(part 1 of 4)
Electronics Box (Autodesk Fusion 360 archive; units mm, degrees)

design "Electronics Box" references "USB host shield", "Teensy 4.1", "BTS790 Motor Driver", "half proto board"
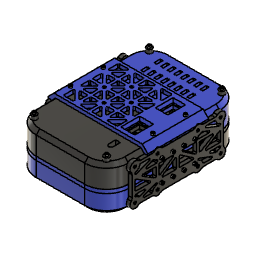
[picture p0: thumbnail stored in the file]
parameter "threadedinsertdiam" = 4.4
parameter "m3screwdiam" = 3.4
parameter "d454" = 6.4625 (= "0.1875 in + ( m3screwdiam / 2 )")
component_insert "Component Insert1"
component_insert "Component Insert2"
component_insert "Component Insert3"
position "Position2"
position "Position3"
component_insert "Component Insert4"
rectangular_pattern "Ё" uSpaceDistance 53 vSpaceDistance 0
rectangular_pattern "Ё" uSpaceDistance -53 vSpaceDistance 0
copy_paste "CutPaste1"
copy_paste "CutPaste2"
copy_paste "CutPaste3"
copy_paste "CutPaste4"
copy_paste "CutPaste5"
copy_paste "CutPaste6"
copy_paste "CutPaste7"
copy_paste "CutPaste8"
copy_paste "CutPaste1"
copy_paste "CutPaste2"
copy_paste "CutPaste3"
position "Position4"
position "Position5"
position "Position6"
position "Position7"
position "Position8"
sketch "Sketch1" plane through (0, 0, -1.65) normal (0, 0, -1) x axis (1, 0, 0)
  line L1 (-25, -25) -> (78, -25)
  line L2 (-25, 184) -> (-25, -25)
  line L3 (78, 184) -> (-25, 184)
  line L4 (78, -25) -> (78, 184)
  line L5 (-31.35, 190.35) -> (-31.35, -31.35)
  line L6 (84.35, 190.35) -> (-31.35, 190.35)
  line L7 (84.35, -31.35) -> (84.35, 190.35)
  line L8 (-31.35, -31.35) -> (84.35, -31.35)
  line L9 (-37.7, 196.7) -> (-37.7, -37.7)
  line L10 (90.7, 196.7) -> (-37.7, 196.7)
  line L11 (90.7, -37.7) -> (90.7, 196.7)
  line L12 (-37.7, -37.7) -> (90.7, -37.7)
  line L13 (90.7, -31.35) -> (84.35, -31.35)
  line L14 (90.7, 190.35) -> (84.35, 190.35)
  circle C1 centre (-20, 179) radius 1.5
  circle C2 centre (20, 179) radius 1.5
  circle C3 centre (20, 139) radius 1.5
  circle C4 centre (-20, 139) radius 1.5
  circle C5 centre (33, 179) radius 1.5
  circle C6 centre (73, 179) radius 1.5
  circle C7 centre (33, 139) radius 1.5
  circle C8 centre (73, 139) radius 1.5
  circle C9 centre (73, 126) radius 1.5
  circle C10 centre (33, 126) radius 1.5
  circle C11 centre (20, 126) radius 1.5
  circle C12 centre (-20, 126) radius 1.5
  circle C13 centre (-20, 86) radius 1.5
  circle C14 centre (20, 86) radius 1.5
  circle C15 centre (20, 73) radius 1.5
  circle C16 centre (20, 33) radius 1.5
  circle C17 centre (-20, 33) radius 1.5
  circle C18 centre (-20, 73) radius 1.5
  circle C19 centre (33, 73) radius 1.5
  circle C20 centre (73, 73) radius 1.5
  circle C21 centre (73, 33) radius 1.5
  circle C22 centre (33, 33) radius 1.5
  circle C23 centre (33, 20) radius 1.5
  circle C24 centre (73, 20) radius 1.5
  circle C25 centre (73, -20) radius 1.5
  circle C26 centre (33, -20) radius 1.5
  circle C27 centre (-20, -20) radius 1.5
  circle C28 centre (20, -20) radius 1.5
  circle C29 centre (20, 20) radius 1.5
  circle C30 centre (-20, 20) radius 1.5
  point P8 (73.5, -25)
  point P9 (78, -20.5)
  point P2 (-25, 179.5)
  point P3 (-20.5, 184)
  point P48 (90.7, -31.35)
  point P49 (90.7, 190.35)
  horizontal L1
  vertical L2
  horizontal L3
  vertical L4
  coincident L1 P8
  coincident L4 P9
  coincident P2 L2
  coincident P3 L3
  coincident L11 P48
  perpendicular L11 L13
  coincident L11 P49
  perpendicular L11 L14
  dimension "d11" = -6.35
  dimension "d12" = -12.7
extrude "Extrude1" new body sketch "Sketch1" profile of C1 C2 C3 C4 C5 C6 C7 C8 C9 C10 C11 C12 C13 C14 C15 C16 C17 C18 C19 C20 C21 C22 C23 C24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 along normal blind 6.35
extrude "Extrude2" add sketch "Sketch1" profile of L5 L6 L8 L11 L9 L10 L12 L13 L14 against normal blind 32
position "Position9"
sketch "Sketch2" plane through (0, 0, 30.35) normal (0, 0, 1) x axis (-1, 0, 0)
  line L1 (-90.7, -31.35) -> (31.35, -31.35)
  line L2 (-90.7, -37.7) -> (-90.7, -31.35)
  line L3 (37.7, -37.7) -> (-90.7, -37.7)
  line L4 (37.7, 196.7) -> (37.7, -37.7)
  line L5 (-90.7, 196.7) -> (37.7, 196.7)
  line L6 (-90.7, 190.35) -> (-90.7, 196.7)
  line L7 (31.35, 190.35) -> (-90.7, 190.35)
  line L8 (31.35, -31.35) -> (31.35, 190.35)
position "Position10"
sketch "Sketch3" plane through (0, 0, 30.35) normal (0, 0, 1) x axis (-1, 0, 0)
  line L1 (-90.7, -31.35) -> (31.35, -31.35)
  line L2 (-90.7, -37.7) -> (-90.7, -31.35)
  line L3 (37.7, -37.7) -> (-90.7, -37.7)
  line L4 (37.7, 196.7) -> (37.7, -37.7)
  line L5 (-90.7, 196.7) -> (37.7, 196.7)
  line L6 (-90.7, 190.35) -> (-90.7, 196.7)
  line L7 (31.35, 190.35) -> (-90.7, 190.35)
  line L8 (31.35, -31.35) -> (31.35, 190.35)
  line L9 (22.075, 30.875) -> (-54.725, 30.875)
  line L10 (-60.825, 141.175) -> (-60.825, 181.075)
  line L11 (14.175, 30.875) -> (31.35, 30.875)
  line L12 (14.175, 190.35) -> (14.175, 30.875)
  line L13 (31.35, 190.35) -> (14.175, 190.35)
  line L14 (31.35, 30.875) -> (31.35, 190.35)
  line L15 (-60.825, 30.875) -> (-46.825, 30.875)
  line L16 (-60.825, 190.35) -> (-60.825, 30.875)
  line L17 (-46.825, 190.35) -> (-60.825, 190.35)
  line L18 (-46.825, 30.875) -> (-46.825, 190.35)
  line L19 (-60.825, 30.875) -> (31.35, 30.875)
  line L20 (-60.825, 16.875) -> (-60.825, 30.875)
  line L21 (31.35, 16.875) -> (-60.825, 16.875)
  line L22 (31.35, 30.875) -> (31.35, 16.875)
  circle C1 centre (-53.175, 56.925) radius 1.5
  circle C2 centre (20.525, 56.925) radius 1.5
  point P9 (31.35, 190.35)
  point P17 (31.35, 190.35)
  point P11 (22.075, 30.875)
  point P8 (-90.7, 190.35)
  point P10 (-54.725, 30.875)
  point P13 (-60.825, 141.175)
  point P19 (-60.825, 30.875)
  point P23 (20.525, 56.925)
  point P22 (-53.175, 56.925)
  point P24 (-60.825, 30.875)
  point P25 (-60.825, 16.875)
  horizontal L11
  vertical L12
  horizontal L13
  vertical L14
  coincident P9 P17
  coincident P11 L11
  horizontal L15
  vertical L16
  horizontal L17
  vertical L18
  coincident P8 L17
  coincident P10 L15
  coincident P13 L16
  horizontal L19
  vertical L20
  horizontal L21
  vertical L22
  coincident P19 L20
  dimension "d15" distance L12 P23 = 6.35
  dimension "d16" distance L18 P22 = 6.35
  dimension "d19" distance P24 P25 = 14
extrude "Extrude3" add sketch "Sketch3" profile of L7 L8 L9 L10 L11 L12 L13 L14 L15 L16 L17 L18 C1 C2 L19 L20 L21 L22 against normal blind 6.35
component_insert "Component Insert5"
position "Position11"
component_insert "Component Insert6"
position "Position12"
position "Position13"
position "Position14"
position "Position15"
position "Position16"
position "Position17"
position "Position18"
position "Position19"
extrude "Extrude4" new body sketch "Sketch3" profile of L1 L2 L3 L4 L5 L6 L7 L8 L13 L14 L17 L22 along normal blind 25.4
sketch "Sketch4" plane through (0, 0, 55.75) normal (0, 0, 1) x axis (-1, 0, 0)
  line L1 (37.7, -37.7) -> (-90.7, -37.7)
  line L2 (37.7, 196.7) -> (37.7, -37.7)
  line L3 (-90.7, 196.7) -> (37.7, 196.7)
  line L4 (-90.7, -37.7) -> (-90.7, 196.7)
  point P3 (37.7, 196.7)
  point P6 (37.7, 196.7)
  point P2 (-90.7, -37.7)
  point P4 (-90.7, -37.7)
  horizontal L1
  vertical L2
  horizontal L3
  vertical L4
  coincident P3 P6
  coincident P2 P4
extrude "Extrude5" add sketch "Sketch4" along normal blind 6.35
sketch "Sketch5" plane through (-37.7, 0, 0) normal (-1, 0, 0) x axis (0, -1, 0)
  line L1 (115.3556, 46) -> (99.3556, 46)
  line L2 (115.3556, 53) -> (115.3556, 46)
  line L3 (99.3556, 53) -> (115.3556, 53)
  line L4 (99.3556, 46) -> (99.3556, 53)
  line L5 (121.7056, 39.65) -> (93.0056, 39.65)
  line L6 (121.7056, 59.35) -> (121.7056, 39.65)
  line L7 (93.0056, 59.35) -> (121.7056, 59.35)
  line L8 (93.0056, 39.65) -> (93.0056, 59.35)
  line L9 (93.0056, 59.35) -> (121.7056, 59.35)
  line L10 (93.0056, 68.4778) -> (93.0056, 59.35)
  line L11 (121.7056, 68.4778) -> (93.0056, 68.4778)
  line L12 (121.7056, 59.35) -> (121.7056, 68.4778)
  line L13 (163.2111, 46) -> (155.7111, 46)
  line L14 (163.2111, 49.07) -> (163.2111, 46)
  line L15 (155.7111, 49.07) -> (163.2111, 49.07)
  line L16 (155.7111, 46) -> (155.7111, 49.07)
  line L17 (169.5611, 39.65) -> (149.3611, 39.65)
  line L18 (169.5611, 55.42) -> (169.5611, 39.65)
  line L19 (149.3611, 55.42) -> (169.5611, 55.42)
  line L20 (149.3611, 39.65) -> (149.3611, 55.42)
  horizontal L9
  vertical L10
  horizontal L11
  vertical L12
  dimension "d24" = 6.35
  dimension "d25" = 6.35
copy_paste "CutPaste1"
copy_paste "CutPaste2"
copy_paste "CutPaste3"
copy_paste "CutPaste4"
extrude "Extrude6" cut sketch "Sketch5" profile of L13 L14 L15 L16 L17 L18 L19 L20 against normal blind 10.16
extrude "Extrude7" cut sketch "Sketch5" profile of L1 L2 L3 L4 L5 L6 L7 L8 L9 L10 L11 L12 against normal blind 25.4
sketch "Sketch6" plane through (0, 0, 62.1) normal (0, 0, 1) x axis (-1, 0, 0)
  line L1 (37.7, 121.7056) -> (12.3, 121.7056)
  line L2 (37.7, 196.7) -> (37.7, 121.7056)
  line L3 (-90.7, 196.7) -> (37.7, 196.7)
  line L4 (-90.7, -37.7) -> (-90.7, 196.7)
  line L5 (37.7, -37.7) -> (-90.7, -37.7)
  line L6 (37.7, 93.0056) -> (37.7, -37.7)
  line L7 (12.3, 93.0056) -> (37.7, 93.0056)
  line L8 (12.3, 121.7056) -> (12.3, 93.0056)
  line L9 (-60.825, 16.875) -> (31.35, 16.875)
  line L10 (-90.7, -31.35) -> (31.35, -31.35)
  line L11 (31.35, -31.35) -> (31.35, 190.35)
  line L12 (23.4125, -1.3625) -> (19.3525, -1.3625)
  line L13 (23.4125, 8.9375) -> (23.4125, -1.3625)
  line L14 (19.3525, 8.9375) -> (23.4125, 8.9375)
  line L15 (19.3525, -1.3625) -> (19.3525, 8.9375)
  line L16 (23.4125, 8.9375) -> (19.3525, -1.3625)
  line L17 (19.3525, 8.9375) -> (23.4125, -1.3625)
  line L18 (14.59, 13.7) -> (28.175, 13.7)
  line L19 (14.59, -6.125) -> (14.59, 13.7)
  line L20 (28.175, -6.125) -> (14.59, -6.125)
  line L21 (28.175, 13.7) -> (28.175, -6.125)
  line L22 (23.4125, -17.0625) -> (19.3525, -17.0625)
  line L23 (23.4125, -6.7625) -> (23.4125, -17.0625)
  line L24 (19.3525, -6.7625) -> (23.4125, -6.7625)
  line L25 (19.3525, -17.0625) -> (19.3525, -6.7625)
  line L26 (23.4125, -6.7625) -> (19.3525, -17.0625)
  line L27 (19.3525, -6.7625) -> (23.4125, -17.0625)
  line L28 (28.175, -2) -> (28.175, -21.825)
  line L29 (14.59, -2) -> (28.175, -2)
  line L30 (14.59, -21.825) -> (14.59, -2)
  line L31 (28.175, -21.825) -> (14.59, -21.825)
  point P20 (21.3825, 3.7875)
  point P29 (21.3825, -11.9125)
  point P16 (19.3525, -1.3625)
  point P17 (23.4125, -1.3625)
  point P19 (19.3525, 8.9375)
  point P25 (19.3525, -17.0625)
  point P26 (23.4125, -17.0625)
  point P28 (19.3525, -6.7625)
  horizontal L12
  perpendicular L12 L13
  parallel L12 L14
  parallel L13 L15
  coincident L16 P20
  coincident L17 P20
  horizontal L22
  perpendicular L22 L23
  parallel L22 L24
  parallel L23 L25
  coincident L26 P29
  coincident L27 P29
  dimension "d36" distance P16 P17 = 4.06
  dimension "d37" distance P16 P19 = 10.3
  dimension "d38" = 4.7625 (= "( 3 / 16 ) * 1 in")
  dimension "d39" distance L11 L21 = 3.175 (= "( 1 / 8 ) * 1 in")
  dimension "d40" distance L9 L18 = 3.175 (= "( 1 / 8 ) * 1 in")
  dimension "d47" distance P25 P26 = 4.06 (= "d36")
  dimension "d48" distance P25 P28 = 10.3 (= "d37")
  dimension "d49" = 4.7625 (= "( 3 / 16 ) * 1 in")
  dimension "d50" distance L11 L28 = 3.175 (= "d39")
  dimension "d51" distance L10 L31 = 9.525
sketch "Sketch7" plane through (0, 0, 62.1) normal (0, 0, 1) x axis (-1, 0, 0)
  line L1 (-74.31, 13.7) -> (28.175, 13.7)
  line L2 (-74.31, -21.825) -> (-74.31, 13.7)
  line L3 (28.175, -21.825) -> (-74.31, -21.825)
  line L4 (28.175, 13.7) -> (28.175, -21.825)
  point P2 (28.175, 13.7)
  point P3 (28.175, 13.7)
  horizontal L1
  vertical L2
  horizontal L3
  vertical L4
  coincident P2 P3
extrude "Extrude13" cut of existing geometry blind -0.3302
extrude "Extrude14" add of existing geometry blind 0.0002 (= "7.791E-06 in")
split "Split1"
split "Split2"
split "Split3"
combine "Combine2"
extrude "Extrude15" new body of existing geometry blind 25.4
extrude "Extrude16" new body of existing geometry blind 25.4
combine "Combine3"
combine "Combine4"
extrude "Extrude17" new body of existing geometry blind 6.35
extrude "Extrude18" add of existing geometry blind 223.52
extrude "Extrude19" new body of existing geometry blind 32.004
combine "Combine5"
combine "Combine6"
extrude "Extrude21" add of existing geometry blind 2.54
extrude "Extrude22" cut of existing geometry blind -27.94
position "Position20"
extrude "Extrude23" add of existing geometry blind 12.7
extrude "Extrude24" add of existing geometry blind 12.7
extrude "Extrude25" cut of existing geometry blind -12.7
split "Split4"
extrude "Extrude26" cut of existing geometry blind -12.7
move_face "MoveFace1"
fillet "Fillet2" radius 31.75
fillet "Fillet3" radius 38.1
chamfer "Chamfer3" distance 6.35
chamfer "Chamfer2" distance 2.6303
sketch "Sketch10" plane through (0, 0, 62.1) normal (0, 0, 1) x axis (-1, 0, 0)
  line L1 (-84.35, -31.35) -> (-0.4, -31.35)
  line L2 (-84.35, 14.65) -> (-84.35, -31.35)
  line L3 (-0.4, 14.65) -> (-84.35, 14.65)
  line L4 (-0.4, -31.35) -> (-0.4, 14.65)
  line L5 (-4.46, 14.65) -> (-0.4, 14.65)
  line L6 (-4.46, 4.35) -> (-4.46, 14.65)
  line L7 (-0.4, 4.35) -> (-4.46, 4.35)
  line L8 (-0.4, 14.65) -> (-0.4, 4.35)
  line L9 (-4.46, -8.35) -> (-0.4, -8.35)
  line L10 (-4.46, -18.65) -> (-4.46, -8.35)
  line L11 (-0.4, -18.65) -> (-4.46, -18.65)
  line L12 (-0.4, -8.35) -> (-0.4, -18.65)
  point P2 (-0.4, -31.35)
  point P4 (-0.4, -31.35)
  point P3 (-84.35, -31.35)
  point P5 (-84.35, -31.35)
  point P11 (-0.4, -8.35)
  point P9 (-4.46, 4.35)
  point P10 (-0.4, 4.35)
  point P8 (-4.46, 14.65)
  point P13 (-4.46, -18.65)
  point P14 (-0.4, -18.65)
  point P12 (-4.46, -8.35)
  horizontal L1
  vertical L2
  horizontal L3
  vertical L4
  coincident P2 P4
  coincident P3 P5
  horizontal L5
  vertical L6
  horizontal L7
  vertical L8
  horizontal L9
  vertical L10
  horizontal L11
  vertical L12
  coincident L4 P11
  dimension "d112" distance P9 P10 = 4.06
  dimension "d113" distance P8 P9 = 10.3
  dimension "d114" distance P13 P14 = 4.06 (= "d112")
  dimension "d115" distance P12 P13 = 10.3 (= "d113")
  dimension "d116" distance L1 L11 = 12.7
  dimension "d117" distance L7 L9 = 12.7
extrude "Extrude28" cut sketch "Sketch10" profile of L5 L6 L7 L8 L9 L10 L11 L12 against normal blind 27.94
rectangular_pattern "R-Pattern2" uSpaceDistance -79.89 (= "-3.3051181102362204 in + 4.06 mm") vSpaceDistance 0
sketch "Sketch11" plane through (0, 0, 55.75) normal (0, 0, -1) x axis (1, 0, 0)
  line L1 (84.35, 14.65) -> (80.29, 14.65)
  line L2 (84.35, 4.35) -> (84.35, 14.65)
  line L3 (80.29, 4.35) -> (84.35, 4.35)
  line L4 (80.29, 14.65) -> (80.29, 4.35)
  line L5 (84.35, -8.35) -> (80.29, -8.35)
  line L6 (84.35, -18.65) -> (84.35, -8.35)
  line L7 (80.29, -18.65) -> (84.35, -18.65)
  line L8 (80.29, -8.35) -> (80.29, -18.65)
  line L9 (72.9371, 14.65) -> (68.8771, 14.65)
  line L10 (72.9371, 4.35) -> (72.9371, 14.65)
  line L11 (68.8771, 4.35) -> (72.9371, 4.35)
  line L12 (68.8771, 14.65) -> (68.8771, 4.35)
  line L13 (72.9371, -8.35) -> (68.8771, -8.35)
  line L14 (72.9371, -18.65) -> (72.9371, -8.35)
  line L15 (68.8771, -18.65) -> (72.9371, -18.65)
  line L16 (68.8771, -8.35) -> (68.8771, -18.65)
  line L17 (61.5243, 14.65) -> (57.4643, 14.65)
  line L18 (61.5243, 4.35) -> (61.5243, 14.65)
  line L19 (57.4643, 4.35) -> (61.5243, 4.35)
  line L20 (57.4643, 14.65) -> (57.4643, 4.35)
  line L21 (61.5243, -8.35) -> (57.4643, -8.35)
  line L22 (61.5243, -18.65) -> (61.5243, -8.35)
  line L23 (57.4643, -18.65) -> (61.5243, -18.65)
  line L24 (57.4643, -8.35) -> (57.4643, -18.65)
  line L25 (50.1114, 14.65) -> (46.0514, 14.65)
  line L26 (50.1114, 4.35) -> (50.1114, 14.65)
  line L27 (46.0514, 4.35) -> (50.1114, 4.35)
  line L28 (46.0514, 14.65) -> (46.0514, 4.35)
  line L29 (50.1114, -8.35) -> (46.0514, -8.35)
  line L30 (50.1114, -18.65) -> (50.1114, -8.35)
  line L31 (46.0514, -18.65) -> (50.1114, -18.65)
  line L32 (46.0514, -8.35) -> (46.0514, -18.65)
  line L33 (38.6986, 14.65) -> (34.6386, 14.65)
  line L34 (38.6986, 4.35) -> (38.6986, 14.65)
  line L35 (34.6386, 4.35) -> (38.6986, 4.35)
  line L36 (34.6386, 14.65) -> (34.6386, 4.35)
  line L37 (38.6986, -8.35) -> (34.6386, -8.35)
  line L38 (38.6986, -18.65) -> (38.6986, -8.35)
  line L39 (34.6386, -18.65) -> (38.6986, -18.65)
  line L40 (34.6386, -8.35) -> (34.6386, -18.65)
  line L41 (27.2857, 14.65) -> (23.2257, 14.65)
  line L42 (27.2857, 4.35) -> (27.2857, 14.65)
  line L43 (23.2257, 4.35) -> (27.2857, 4.35)
  line L44 (23.2257, 14.65) -> (23.2257, 4.35)
  line L45 (27.2857, -8.35) -> (23.2257, -8.35)
  line L46 (27.2857, -18.65) -> (27.2857, -8.35)
  line L47 (23.2257, -18.65) -> (27.2857, -18.65)
  line L48 (23.2257, -8.35) -> (23.2257, -18.65)
  line L49 (15.8729, 14.65) -> (11.8129, 14.65)
  line L50 (15.8729, 4.35) -> (15.8729, 14.65)
  line L51 (11.8129, 4.35) -> (15.8729, 4.35)
  line L52 (11.8129, 14.65) -> (11.8129, 4.35)
  line L53 (15.8729, -8.35) -> (11.8129, -8.35)
  line L54 (15.8729, -18.65) -> (15.8729, -8.35)
  line L55 (11.8129, -18.65) -> (15.8729, -18.65)
  line L56 (11.8129, -8.35) -> (11.8129, -18.65)
  line L57 (4.46, 14.65) -> (0.4, 14.65)
  line L58 (4.46, 4.35) -> (4.46, 14.65)
  line L59 (0.4, 4.35) -> (4.46, 4.35)
  line L60 (0.4, 14.65) -> (0.4, 4.35)
  line L61 (4.46, -8.35) -> (0.4, -8.35)
  line L62 (4.46, -18.65) -> (4.46, -8.35)
  line L63 (0.4, -18.65) -> (4.46, -18.65)
  line L64 (0.4, -8.35) -> (0.4, -18.65)
  line L65 (90.7, 21) -> (-5.95, 21)
  line L66 (90.7, -34.525) -> (90.7, 21)
  line L67 (-5.95, -34.525) -> (90.7, -34.525)
  line L68 (-5.95, 21) -> (-5.95, -34.525)
  point P64 (4.46, -18.65)
  point P62 (0.4, -8.35)
  point P59 (4.46, 14.65)
  point P7 (84.35, -8.35)
  horizontal L65
  vertical L66
  horizontal L67
  vertical L68
  dimension "d124" distance P64 L67 = 15.875
  dimension "d125" distance P62 L68 = 6.35
  dimension "d126" distance P59 L65 = 6.35 (= "d125")
  dimension "d127" distance P7 L66 = 6.35 (= "d125")
extrude "Extrude29" add sketch "Sketch11" profile of L1 L2 L3 L4 L5 L6 L7 L8 L9 L10 L11 L12 L13 L14 L15 L16 L17 L18 L19 L20 L21 L22 L23 L24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 along normal blind 18
work_plane "WorkPlane2"
extrude "Extrude30" cut of existing geometry blind -0.8056
extrude "Extrude31" cut of existing geometry blind -0.8056
split "Split5"
extrude "Extrude34" new body of existing geometry blind 61.6204
extrude "Extrude35" new body of existing geometry blind 41.8846
combine "Combine7"
fillet "Fillet4" radius 38.1
split "Split6"
split "Split7"
remove_body "RemoveBody1"
remove_body "RemoveBody2"
position "Position21"
extrude "Extrude36" cut of existing geometry blind -12.7
extrude "Extrude37" add of existing geometry blind 12.7
split "Split8"
extrude "Extrude38" add of existing geometry blind 35.56
delete_face "DeleteFace1"
sketch "Sketch14" plane through (0, 0, 30.35) normal (0, 0, 1) x axis (-1, 0, 0)
  line L1 (-84.3454, -37.7096) -> (-0.4, -37.7096)
  line L2 (1.475, 79.5) -> (37.7, 79.5)
  line L3 (1.475, 18.175) -> (1.475, 79.5)
  line L4 (-59.525, 18.175) -> (1.475, 18.175)
  line L5 (-59.525, 79.5) -> (-59.525, 18.175)
  line L6 (-122.4454, 79.5) -> (-59.525, 79.5)
  line L7 (-122.4454, 0.3904) -> (-122.4454, 79.5)
  line L8 (-0.4, -37.7096) -> (-84.3454, -37.7096)
  line L9 (37.7, 79.5) -> (37.7, 0.3904)
  line L10 (37.7, 79.5) -> (1.475, 79.5)
  line L11 (37.7, 158.6) -> (37.7, 79.5)
  line L12 (-84.3454, 196.7) -> (-0.4, 196.7)
  line L13 (-122.4454, 79.5) -> (-122.4454, 158.6)
  line L14 (-59.525, 79.5) -> (-122.4454, 79.5)
  line L15 (-59.525, 177.65) -> (-59.525, 79.5)
  line L16 (1.475, 177.65) -> (-59.525, 177.65)
  line L17 (1.475, 79.5) -> (1.475, 177.65)
  line L18 (14.175, 92.2) -> (14.175, 179.4021)
  line L19 (25, 92.2) -> (14.175, 92.2)
  line L20 (25, 158.6) -> (25, 92.2)
  line L21 (-72.225, 184) -> (-72.225, 92.2)
  line L22 (-84.3454, 184) -> (-72.225, 184)
  line L23 (-109.7454, 92.2) -> (-109.7454, 158.6)
  line L24 (-72.225, 92.2) -> (-109.7454, 92.2)
  line L25 (-0.4, -25.0096) -> (-84.3454, -25.0096)
  line L26 (25, 66.8) -> (25, 0.3904)
  line L27 (14.175, 66.8) -> (25, 66.8)
  line L28 (14.175, 5.475) -> (14.175, 66.8)
  line L29 (-72.225, 5.475) -> (14.175, 5.475)
  line L30 (-72.225, 66.8) -> (-72.225, 5.475)
  line L31 (-109.7454, 66.8) -> (-72.225, 66.8)
  line L32 (-109.7454, 0.3904) -> (-109.7454, 66.8)
  line L33 (-109.7454, 92.2) -> (-109.7454, 66.8)
  line L34 (-72.225, 18.175) -> (14.175, 18.175)
  line L35 (-109.7454, 5.475) -> (-72.225, 5.475)
  line L36 (-73.525, 184) -> (-73.525, 5.475)
  line L37 (25, 18.175) -> (14.175, 18.175)
  line L38 (-73.525, 18.175) -> (-72.225, 18.175)
  arc A1 centre (-84.3454, 0.3904) radius 38.1 clockwise from (-84.3454, -37.7096) to (-122.4454, 0.3904)
  arc A2 centre (-0.4, 0.3904) radius 38.1 clockwise from (37.7, 0.3904) to (-0.4, -37.7096)
  arc A3 centre (-0.4, 158.6) radius 38.1 clockwise from (-0.4, 196.7) to (37.7, 158.6)
  arc A4 centre (-84.3454, 158.6) radius 38.1 clockwise from (-122.4454, 158.6) to (-84.3454, 196.7)
  arc A5 centre (-0.4, 158.6) radius 25.4 clockwise from (14.175, 179.4021) to (25, 158.6)
  arc A6 centre (-84.3454, 158.6) radius 25.4 clockwise from (-109.7454, 158.6) to (-84.3454, 184)
  arc A7 centre (-0.4, 0.3904) radius 25.4 clockwise from (25, 0.3904) to (-0.4, -25.0096)
  arc A8 centre (-84.3454, 0.3904) radius 25.4 clockwise from (-84.3454, -25.0096) to (-109.7454, 0.3904)
  point P51 (14.175, 18.175)
  point P52 (-72.225, 18.175)
  point P6 (1.475, 18.175)
  point P55 (-109.7454, 5.475)
  point P56 (-73.525, 5.475)
  point P53 (-73.525, 24.275)
  point P58 (25, 18.175)
  point P59 (-73.525, 18.175)
  coincident L28 P51
  coincident L30 P52
  perpendicular L30 L34
  coincident P6 L34
  coincident L32 P55
  perpendicular L32 L35
  coincident L35 P56
  perpendicular L35 L36
  coincident P53 L36
  coincident L26 P58
  perpendicular L26 L37
  coincident L36 P59
  perpendicular L36 L38
  dimension "d158" = -12.7
  dimension "d159" = -12.7
extrude "Extrude39" cut sketch "Sketch14" profile of L4 L6 L14 A6 L24 L22 L23 L31 L25 L28 A7 L26 L29 L30 L32 A8 L33 L34 L35 L36 L37 L38 against normal blind 20.32
extrude "Extrude40" add of existing geometry blind 3.175
extrude "Extrude41" add of existing geometry blind 43.18
sketch "Sketch15" plane through (0, -79.5, 0) normal (0, -1, 0) x axis (1, 0, 0)
  line L1 (122.45, 30.35) -> (116.1, 30.35)
  line L2 (122.45, 55.75) -> (122.45, 30.35)
  line L3 (116.1, 62.1) -> (122.45, 55.75)
  line L4 (-31.35, 62.1) -> (116.1, 62.1)
  line L5 (-37.7, 55.75) -> (-31.35, 62.1)
  line L6 (-37.7, 30.35) -> (-37.7, 55.75)
  line L7 (-31.35, 30.35) -> (-37.7, 30.35)
  line L8 (-31.35, 53.1197) -> (-31.35, 30.35)
  line L9 (-28.7197, 55.75) -> (-31.35, 53.1197)
  line L10 (113.4697, 55.75) -> (-28.7197, 55.75)
  line L11 (116.1, 53.1197) -> (113.4697, 55.75)
  line L12 (116.1, 30.35) -> (116.1, 53.1197)
  line L13 (116.1, 62.1) -> (-31.35, 62.1)
  line L14 (116.1, 62.1) -> (122.45, 55.75)
  line L15 (122.45, -8) -> (122.45, 55.75)
  point P17 (-31.35, 62.1)
  point P18 (-31.35, 62.1)
  point P16 (116.1, 62.1)
  point P19 (116.1, 62.1)
  point P15 (122.45, 55.75)
  point P20 (122.45, 55.75)
  point P14 (122.45, -8)
  point P21 (122.45, -8)
  coincident P17 P18
  coincident P16 P19
  coincident P15 P20
  coincident P14 P21
sketch "Sketch16" plane through (0, 0, -8) normal (0, 0, -1) x axis (1, 0, 0)
  line L1 (-37.7, 79.5) -> (122.45, 79.5)
  line L2 (-37.7, 0.4) -> (-37.7, 79.5)
  line L3 (84.35, -37.7) -> (0.4, -37.7)
  line L4 (122.45, 79.5) -> (122.45, 0.4)
  line L5 (128.8, 79.5) -> (122.45, 79.5)
  line L6 (128.8, 41.4) -> (128.8, 79.5)
  line L7 (122.45, 41.4) -> (128.8, 41.4)
  line L8 (122.45, 79.5) -> (122.45, 41.4)
  arc A1 centre (0.4, 0.4) radius 38.1 clockwise from (0.4, -37.7) to (-37.7, 0.4)
  arc A2 centre (84.35, 0.4) radius 38.1 clockwise from (122.45, 0.4) to (84.35, -37.7)
  point P2 (122.45, 79.5)
  point P11 (122.45, 79.5)
  point P13 (128.8, 41.4)
  point P14 (122.45, 41.4)
  point P12 (128.8, 79.5)
  horizontal L5
  vertical L6
  horizontal L7
  vertical L8
  coincident P2 P11
  dimension "d166" distance P13 P14 = 6.35
  dimension "d167" distance P12 P13 = 38.1
sweep "Sweep2" sketch "Sketch16" TwistAngle 0 TaperAngle 0
extrude "Extrude42" cut of existing geometry blind -139.7
sketch "Sketch17" plane through (128.8, 0, 0) normal (1, 0, 0) x axis (0, 1, 0)
  line L1 (-41.4, -8) -> (-79.5, -8)
  line L2 (-41.4, 58.3803) -> (-41.4, -8)
  line L3 (-79.5, 58.3803) -> (-41.4, 58.3803)
  line L4 (-79.5, -8) -> (-79.5, 58.3803)
  line L5 (-79.5, 24) -> (-79.5, -1.65)
  line L6 (-0.4, 24) -> (-79.5, 24)
  line L7 (-0.4, -1.65) -> (-0.4, 24)
  line L8 (-79.5, -1.65) -> (-0.4, -1.65)
  line L9 (-41.4, 58.3803) -> (-41.4, -8)
  line L10 (-79.5, 30.35) -> (-0.4, 30.35)
  line L11 (-79.5, 53.1197) -> (-79.5, 30.35)
  line L12 (-0.4, 53.1197) -> (-79.5, 53.1197)
  line L13 (-0.4, 30.35) -> (-0.4, 53.1197)
  line L14 (-41.4, 41.7349) -> (-79.5, 41.7349)
  line L15 (-41.4, 11.175) -> (-79.5, 11.175)
  point P16 (-79.5, 41.7349)
  point P17 (-41.4, 41.7349)
  point P18 (-79.5, 11.175)
  point P19 (-41.4, 11.175)
  point P20 (-69.975, 11.175)
  point P21 (-50.925, 11.175)
  point P22 (-50.925, 41.7349)
  point P23 (-69.975, 41.7349)
  midpoint L11 P16
  coincident L9 P17
  perpendicular L9 L14
  midpoint L5 P18
  coincident L9 P19
  perpendicular L9 L15
  coincident L15 P20
  coincident L15 P21
  coincident L14 P22
  coincident L14 P23
  dimension "d180" distance P18 P20 = 9.525
  dimension "d181" distance P19 P21 = 9.525 (= "d180")
  dimension "d182" distance P16 P23 = 9.525 (= "d180")
  dimension "d183" distance P17 P22 = 9.525 (= "d180")
hole "Hole1" HoleDepth 25.4 HoleDiameter 3.4 (= "m3screwdiam") TipAngle 180
sketch "Sketch18" plane through (122.45, 0, 0) normal (1, 0, 0) x axis (0, 1, 0)
  line L1 (-79.5, -8) -> (-79.5, 24)
  line L2 (-0.4, -8) -> (-79.5, -8)
  line L3 (-0.4, 24) -> (-0.4, -8)
  line L4 (-79.5, 24) -> (-0.4, 24)
hole "Hole2" HoleDepth 177.8 HoleDiameter 4.4 (= "threadedinsertdiam") TipAngle 180
mirror "Mirror3" mirrorStitchTolerance 0.1016
mirror "Mirror1" mirrorStitchTolerance 0.1016
work_plane "WorkPlane5"
mirror "Mirror2" mirrorStitchTolerance 0.1016
sketch "Sketch19" plane through (122.45, 0, 0) normal (1, 0, 0) x axis (0, 1, 0)
  line L1 (-79.5, 30.35) -> (-158.6, 30.35)
  line L2 (-158.6, 55.75) -> (-79.5, 55.75)
  line L3 (-158.6, 30.35) -> (-158.6, 55.75)
  line L4 (-41.4, -8) -> (-117.6, -8)
  line L5 (-41.4, 58.3803) -> (-41.4, -8)
  line L6 (-117.6, 58.3803) -> (-41.4, 58.3803)
  line L7 (-117.6, -8) -> (-117.6, 58.3803)
  circle C1 centre (-108.075, 11.175) radius 1.7
  circle C2 centre (-89.025, 41.7349) radius 1.7
  circle C3 centre (-108.075, 41.7349) radius 1.7
  circle C4 centre (-89.025, 11.175) radius 1.7
  circle C5 centre (-69.975, 11.175) radius 1.7
  circle C6 centre (-50.925, 41.7349) radius 1.7
  circle C7 centre (-69.975, 41.7349) radius 1.7
  circle C8 centre (-50.925, 11.175) radius 1.7
hole "Hole3" HoleDepth 190.5 HoleDiameter 4.4 (= "threadedinsertdiam") TipAngle 180
sketch "Sketch20" plane through (0, 0, -1.65) normal (0, 0, 1) x axis (-1, 0, 0)
  line L1 (-116.1, 0.4) -> (-116.1, 79.5)
  line L2 (31.35, 79.5) -> (31.35, 0.4)
  line L3 (-106.8006, -22.0506) -> (-84.35, 0.4)
  line L4 (-124.8544, -28.0129) -> (-111.2908, -14.4492)
  line L5 (-99.1992, -26.5408) -> (-112.7629, -40.1044)
  line L6 (-118.8086, -34.0586) -> (-105.245, -20.495)
  line L7 (-83.1465, 51.2) -> (-116.1, 51.2)
  line L8 (-136.6984, 59.75) -> (-113.9, 59.75)
  line L9 (-113.9, 42.65) -> (-136.6984, 42.65)
  line L10 (-136.6984, 51.2) -> (-113.9, 51.2)
  line L11 (-122.45, 0.4) -> (-122.45, 79.5)
  arc A1 centre (-84.35, 0.4) radius 31.75 clockwise from (-84.35, -31.35) to (-116.1, 0.4)
  arc A2 centre (-0.4, 0.4) radius 31.75 clockwise from (31.35, 0.4) to (-0.4, -31.35)
  circle C1 centre (-105.245, -20.495) radius 2.2
  circle C2 centre (-105.245, -20.495) radius 8.55
  arc A3 centre (-118.8086, -34.0586) radius 8.55 clockwise from (-112.7629, -40.1044) to (-124.8544, -28.0129)
  arc A4 centre (-105.245, -20.495) radius 8.55 clockwise from (-111.2908, -14.4492) to (-99.1992, -26.5408)
  arc A5 centre (-84.35, 0.4) radius 38.1 clockwise from (-84.35, -37.7) to (-122.45, 0.4)
  circle C3 centre (-113.9, 51.2) radius 2.2
  circle C4 centre (-113.9, 51.2) radius 8.55
  arc A6 centre (-136.6984, 51.2) radius 8.55 clockwise from (-136.6984, 42.65) to (-136.6984, 59.75)
  arc A7 centre (-113.9, 51.2) radius 8.55 clockwise from (-113.9, 59.75) to (-113.9, 42.65)
  point P4 (-84.35, 0.4)
  point P12 (-84.35, 0.4)
  point P13 (-106.8006, -22.0506)
  point P10 (-105.245, -20.495)
  point P18 (-105.245, -20.495)
  point P23 (-116.1, 51.2)
  point P25 (-116.1, 51.2)
  point P24 (-113.9, 51.2)
  point P32 (-113.9, 51.2)
  point P2 (-116.1, 0.4)
  coincident P4 P12
  midpoint A1 P13
  coincident P10 L3
  tangent L4 A3
  tangent A3 L5
  parallel L4 L5
  tangent L5 A4
  tangent L4 A4
  coincident P10 P18
  collinear L3 L6
  tangent C2 A4
  coincident L1 P23
  coincident P23 P25
  perpendicular L1 L7
  coincident P24 L7
  tangent L8 A6
  tangent A6 L9
  parallel L8 L9
  tangent L9 A7
  tangent L8 A7
  perpendicular L1 L10
  coincident P24 P32
  tangent C4 A7
  tangent A1 C1
  tangent L1 C3
  dimension "d197" diameter C1 = 4.4 (= "threadedinsertdiam")
  dimension "d198" = 6.35
  dimension "d199" distance P2 P23 = 50.8
  dimension "d200" diameter C3 = 4.4 (= "threadedinsertdiam")
  dimension "d201" = 6.35
extrude "Extrude43" new body sketch "Sketch20" profile of A1 L1 C1 L4 L5 A4 C3 L8 L9 A7 along normal blind 25.65
sketch "Sketch21" plane through (0, 0, 24) normal (0, 0, 1) x axis (-1, 0, 0)
  line L1 (-116.1, 59.75) -> (-113.9, 59.75)
  line L2 (-116.1, 42.65) -> (-116.1, 59.75)
  line L3 (-113.9, 42.65) -> (-116.1, 42.65)
  arc A1 centre (-113.9, 51.2) radius 8.55 clockwise from (-113.9, 59.75) to (-113.9, 42.65)
hole "Hole4" HoleDepth 10 HoleDiameter 4.4 (= "threadedinsertdiam") TipAngle 180
mirror "Mirror4" mirrorStitchTolerance 0.1016
mirror "Mirror5" mirrorStitchTolerance 0.1016
extrude "Extrude46" new body of existing geometry blind 15.24
extrude "Extrude47" new body of existing geometry blind 12.7
combine "Combine8"
combine "Combine9"
sketch "Sketch22" plane through (0, 0, 30.35) normal (0, 0, 1) x axis (-1, 0, 0)
  line L1 (-73.525, 79.5) -> (-73.525, 184)
  line L2 (-59.525, 79.5) -> (-73.525, 79.5)
  line L3 (-59.525, 174.475) -> (-59.525, 79.5)
  line L4 (1.475, 174.475) -> (-59.525, 174.475)
  line L5 (1.475, 79.5) -> (1.475, 174.475)
  line L6 (37.7, 79.5) -> (1.475, 79.5)
  line L7 (37.7, 158.6) -> (37.7, 79.5)
  line L8 (-84.3454, 196.7) -> (-0.4, 196.7)
  line L9 (-122.4454, 79.5) -> (-122.4454, 158.6)
  line L10 (-109.7454, 79.5) -> (-122.4454, 79.5)
  line L11 (-109.7454, 158.6) -> (-109.7454, 79.5)
  line L12 (-73.525, 184) -> (-84.3454, 184)
  line L13 (-59.525, 18.175) -> (-109.7454, 18.175)
  line L14 (-59.525, 79.5) -> (-59.525, 18.175)
  line L15 (-122.4454, 79.5) -> (-59.525, 79.5)
  line L16 (-122.4454, 0.3904) -> (-122.4454, 79.5)
  line L17 (-0.4, -37.7096) -> (-84.3454, -37.7096)
  line L18 (37.7, 79.5) -> (37.7, 0.3904)
  line L19 (1.475, 79.5) -> (37.7, 79.5)
  line L20 (1.475, 18.175) -> (1.475, 79.5)
  line L21 (25, 18.175) -> (1.475, 18.175)
  line L22 (25, 0.3904) -> (25, 18.175)
  line L23 (-84.3454, -25.0096) -> (-0.4, -25.0096)
  line L24 (-109.7454, 18.175) -> (-109.7454, 0.3904)
  line L25 (-0.4, 190.35) -> (-84.35, 190.35)
  line L26 (14.4492, 185.5408) -> (15.1755, 186.267)
  line L27 (27.267, 174.1755) -> (26.5408, 173.4492)
  line L28 (31.35, 116.35) -> (31.35, 158.6)
  line L29 (29.15, 116.35) -> (31.35, 116.35)
  line L30 (31.35, 99.25) -> (29.15, 99.25)
  line L31 (31.35, 79.5) -> (31.35, 99.25)
  line L32 (37.7, 79.5) -> (31.35, 79.5)
  line L33 (37.7, 158.6) -> (37.7, 79.5)
  line L34 (-84.35, 196.7) -> (-0.4, 196.7)
  line L35 (-122.45, 79.5) -> (-122.45, 158.6)
  line L36 (-116.1, 79.5) -> (-122.45, 79.5)
  line L37 (-116.1, 99.25) -> (-116.1, 79.5)
  line L38 (-113.9, 99.25) -> (-116.1, 99.25)
  line L39 (-116.1, 116.35) -> (-113.9, 116.35)
  line L40 (-116.1, 158.6) -> (-116.1, 116.35)
  line L41 (-111.2908, 173.4492) -> (-112.017, 174.1755)
  line L42 (-99.9255, 186.267) -> (-99.1992, 185.5408)
  line L43 (-116.1, 79.5) -> (-116.1, 59.75)
  line L44 (-122.45, 79.5) -> (-116.1, 79.5)
  line L45 (-122.45, 0.4) -> (-122.45, 79.5)
  line L46 (-0.4, -37.7) -> (-84.35, -37.7)
  line L47 (37.7, 79.5) -> (37.7, 0.4)
  line L48 (31.35, 79.5) -> (37.7, 79.5)
  line L49 (31.35, 59.75) -> (31.35, 79.5)
  line L50 (29.15, 59.75) -> (31.35, 59.75)
  line L51 (31.35, 42.65) -> (29.15, 42.65)
  line L52 (31.35, 0.4) -> (31.35, 42.65)
  line L53 (26.5408, -14.4492) -> (27.267, -15.1755)
  line L54 (15.1755, -27.267) -> (14.4492, -26.5408)
  line L55 (-84.35, -31.35) -> (-0.4, -31.35)
  line L56 (-99.1992, -26.5408) -> (-99.9255, -27.267)
  line L57 (-112.017, -15.1755) -> (-111.2908, -14.4492)
  line L58 (-116.1, 42.65) -> (-116.1, 0.4)
  line L59 (-113.9, 42.65) -> (-116.1, 42.65)
  line L60 (-116.1, 59.75) -> (-113.9, 59.75)
  arc A1 centre (-0.4, 158.6) radius 38.1 clockwise from (-0.4, 196.7) to (37.7, 158.6)
  arc A2 centre (-84.3454, 158.6) radius 38.1 clockwise from (-122.4454, 158.6) to (-84.3454, 196.7)
  arc A3 centre (-84.3454, 158.6) radius 25.4 clockwise from (-109.7454, 158.6) to (-84.3454, 184)
  arc A4 centre (-113.9, 107.8) radius 8.55 clockwise from (-113.9, 116.35) to (-113.9, 99.25)
  arc A5 centre (-105.245, 179.495) radius 8.55 clockwise from (-99.1992, 185.5408) to (-111.2908, 173.4492)
  arc A6 centre (-105.245, -20.495) radius 8.55 clockwise from (-111.2908, -14.4492) to (-99.1992, -26.5408)
  arc A7 centre (20.495, -20.495) radius 8.55 clockwise from (14.4492, -26.5408) to (26.5408, -14.4492)
  arc A8 centre (-84.3454, 0.3904) radius 38.1 clockwise from (-84.3454, -37.7096) to (-122.4454, 0.3904)
  arc A9 centre (-0.4, 0.3904) radius 38.1 clockwise from (37.7, 0.3904) to (-0.4, -37.7096)
  arc A10 centre (-0.4, 0.3904) radius 25.4 clockwise from (25, 0.3904) to (-0.4, -25.0096)
  arc A11 centre (-84.3454, 0.3904) radius 25.4 clockwise from (-84.3454, -25.0096) to (-109.7454, 0.3904)
  circle C1 centre (-105.245, 179.495) radius 2.2
  circle C2 centre (20.495, 179.495) radius 2.2
  circle C3 centre (-113.9, 107.8) radius 2.2
  circle C4 centre (29.15, 107.8) radius 2.2
  arc A12 centre (-84.35, 158.6) radius 31.75 clockwise from (-99.9255, 186.267) to (-84.35, 190.35)
  arc A13 centre (-0.4, 158.6) radius 31.75 clockwise from (-0.4, 190.35) to (15.1755, 186.267)
  arc A14 centre (20.495, 179.495) radius 8.55 clockwise from (26.5408, 173.4492) to (14.4492, 185.5408)
  arc A15 centre (-0.4, 158.6) radius 31.75 clockwise from (27.267, 174.1755) to (31.35, 158.6)
  arc A16 centre (29.15, 107.8) radius 8.55 clockwise from (29.15, 99.25) to (29.15, 116.35)
  arc A17 centre (-0.4, 158.6) radius 38.1 clockwise from (-0.4, 196.7) to (37.7, 158.6)
  arc A18 centre (-84.35, 158.6) radius 38.1 clockwise from (-122.45, 158.6) to (-84.35, 196.7)
  arc A19 centre (-113.9, 107.8) radius 8.55 clockwise from (-113.9, 116.35) to (-113.9, 99.25)
  arc A20 centre (-84.35, 158.6) radius 31.75 clockwise from (-116.1, 158.6) to (-112.017, 174.1755)
  arc A21 centre (-105.245, 179.495) radius 8.55 clockwise from (-99.1992, 185.5408) to (-111.2908, 173.4492)
  arc A22 centre (-84.35, 0.4) radius 38.1 clockwise from (-84.35, -37.7) to (-122.45, 0.4)
  arc A23 centre (-0.4, 0.4) radius 38.1 clockwise from (37.7, 0.4) to (-0.4, -37.7)
  arc A24 centre (29.15, 51.2) radius 8.55 clockwise from (29.15, 42.65) to (29.15, 59.75)
  arc A25 centre (-0.4, 0.4) radius 31.75 clockwise from (31.35, 0.4) to (27.267, -15.1755)
  arc A26 centre (20.495, -20.495) radius 8.55 clockwise from (14.4492, -26.5408) to (26.5408, -14.4492)
  arc A27 centre (-0.4, 0.4) radius 31.75 clockwise from (15.1755, -27.267) to (-0.4, -31.35)
  arc A28 centre (-84.35, 0.4) radius 31.75 clockwise from (-84.35, -31.35) to (-99.9255, -27.267)
  arc A29 centre (-105.245, -20.495) radius 8.55 clockwise from (-111.2908, -14.4492) to (-99.1992, -26.5408)
  arc A30 centre (-84.35, 0.4) radius 31.75 clockwise from (-112.017, -15.1755) to (-116.1, 0.4)
  arc A31 centre (-113.9, 51.2) radius 8.55 clockwise from (-113.9, 59.75) to (-113.9, 42.65)
  circle C5 centre (-105.245, -20.495) radius 2.2
  circle C6 centre (20.495, -20.495) radius 2.2
  circle C7 centre (29.15, 51.2) radius 2.2
  circle C8 centre (-113.9, 51.2) radius 2.2
extrude "Extrude44" add sketch "Sketch22" profile of L11 A3 A4 A5 A6 A7 A10 A11 against normal blind 6.35
hole "Hole5" HoleDepth 10.0076 HoleDiameter 3.4 (= "m3screwdiam") TipAngle 180
position "Position22"
sketch "Sketch23" plane through (0, 0, -1.65) normal (0, 0, 1) x axis (-1, 0, 0)
  line L1 (-113.9, 59.75) -> (-116.1, 59.75)
  line L2 (-116.1, 42.65) -> (-113.9, 42.65)
  line L3 (-116.1, 0.4) -> (-116.1, 42.65)
  line L4 (-111.2908, -14.4492) -> (-112.017, -15.1755)
  line L5 (-99.9255, -27.267) -> (-99.1992, -26.5408)
  line L6 (-0.4, -31.35) -> (-84.35, -31.35)
  line L7 (14.4492, -26.5408) -> (15.1755, -27.267)
  line L8 (27.267, -15.1755) -> (26.5408, -14.4492)
  line L9 (31.35, 42.65) -> (31.35, 0.4)
  line L10 (29.15, 42.65) -> (31.35, 42.65)
  line L11 (31.35, 59.75) -> (29.15, 59.75)
  line L12 (31.35, 79.5) -> (31.35, 59.75)
  line L13 (-116.1, 79.5) -> (31.35, 79.5)
  line L14 (-116.1, 59.75) -> (-116.1, 79.5)
  line L15 (4.625, 25) -> (9.125, 20.5)
  line L16 (-36.375, 25) -> (4.625, 25)
  line L17 (-40.875, 20.5) -> (-36.375, 25)
  line L18 (-40.875, -20.5) -> (-40.875, 20.5)
  line L19 (-36.375, -25) -> (-40.875, -20.5)
  line L20 (4.625, -25) -> (-36.375, -25)
  line L21 (9.125, -20.5) -> (4.625, -25)
  line L22 (9.125, 20.5) -> (9.125, -20.5)
  line L23 (4.625, 78) -> (9.125, 73.5)
  line L24 (-36.375, 78) -> (4.625, 78)
  line L25 (-40.875, 73.5) -> (-36.375, 78)
  line L26 (-40.875, 32.5) -> (-40.875, 73.5)
  line L27 (-36.375, 28) -> (-40.875, 32.5)
  line L28 (4.625, 28) -> (-36.375, 28)
  line L29 (9.125, 32.5) -> (4.625, 28)
  line L30 (9.125, 73.5) -> (9.125, 32.5)
  line L31 (-48.375, 78) -> (-43.875, 73.5)
  line L32 (-89.375, 78) -> (-48.375, 78)
  line L33 (-93.875, 73.5) -> (-89.375, 78)
  line L34 (-93.875, 32.5) -> (-93.875, 73.5)
  line L35 (-89.375, 28) -> (-93.875, 32.5)
  line L36 (-48.375, 28) -> (-89.375, 28)
  line L37 (-43.875, 32.5) -> (-48.375, 28)
  line L38 (-43.875, 73.5) -> (-43.875, 32.5)
  line L39 (-48.375, 131) -> (-43.875, 126.5)
  line L40 (-89.375, 131) -> (-48.375, 131)
  line L41 (-93.875, 126.5) -> (-89.375, 131)
  line L42 (-93.875, 85.5) -> (-93.875, 126.5)
  line L43 (-89.375, 81) -> (-93.875, 85.5)
  line L44 (-48.375, 81) -> (-89.375, 81)
  line L45 (-43.875, 85.5) -> (-48.375, 81)
  line L46 (-43.875, 126.5) -> (-43.875, 85.5)
  line L47 (4.625, 131) -> (9.125, 126.5)
  line L48 (-36.375, 131) -> (4.625, 131)
  line L49 (-40.875, 126.5) -> (-36.375, 131)
  line L50 (-40.875, 85.5) -> (-40.875, 126.5)
  line L51 (-36.375, 81) -> (-40.875, 85.5)
  line L52 (4.625, 81) -> (-36.375, 81)
  line L53 (9.125, 85.5) -> (4.625, 81)
  line L54 (9.125, 126.5) -> (9.125, 85.5)
  line L55 (-48.375, 184) -> (-43.875, 179.5)
  line L56 (-89.375, 184) -> (-48.375, 184)
  line L57 (-93.875, 179.5) -> (-89.375, 184)
  line L58 (-93.875, 138.5) -> (-93.875, 179.5)
  line L59 (-89.375, 134) -> (-93.875, 138.5)
  line L60 (-48.375, 134) -> (-89.375, 134)
  line L61 (-43.875, 138.5) -> (-48.375, 134)
  line L62 (-43.875, 179.5) -> (-43.875, 138.5)
  line L63 (4.625, 184) -> (9.125, 179.5)
  line L64 (-36.375, 184) -> (4.625, 184)
  line L65 (-40.875, 179.5) -> (-36.375, 184)
  line L66 (-40.875, 138.5) -> (-40.875, 179.5)
  line L67 (-36.375, 134) -> (-40.875, 138.5)
  line L68 (4.625, 134) -> (-36.375, 134)
  line L69 (9.125, 138.5) -> (4.625, 134)
  line L70 (9.125, 179.5) -> (9.125, 138.5)
  line L71 (-48.375, 25) -> (-43.875, 20.5)
  line L72 (-89.375, 25) -> (-48.375, 25)
  line L73 (-93.875, 20.5) -> (-89.375, 25)
  line L74 (-93.875, -20.5) -> (-93.875, 20.5)
  line L75 (-89.375, -25) -> (-93.875, -20.5)
  line L76 (-48.375, -25) -> (-89.375, -25)
  line L77 (-43.875, -20.5) -> (-48.375, -25)
  line L78 (-43.875, 20.5) -> (-43.875, -20.5)
  arc A1 centre (-113.9, 51.2) radius 8.55 clockwise from (-113.9, 59.75) to (-113.9, 42.65)
  arc A2 centre (-84.35, 0.4) radius 31.75 clockwise from (-112.017, -15.1755) to (-116.1, 0.4)
  arc A3 centre (-105.245, -20.495) radius 8.55 clockwise from (-111.2908, -14.4492) to (-99.1992, -26.5408)
  arc A4 centre (-84.35, 0.4) radius 31.75 clockwise from (-84.35, -31.35) to (-99.9255, -27.267)
  arc A5 centre (-0.4, 0.4) radius 31.75 clockwise from (15.1755, -27.267) to (-0.4, -31.35)
  arc A6 centre (20.495, -20.495) radius 8.55 clockwise from (14.4492, -26.5408) to (26.5408, -14.4492)
  arc A7 centre (-0.4, 0.4) radius 31.75 clockwise from (31.35, 0.4) to (27.267, -15.1755)
  arc A8 centre (29.15, 51.2) radius 8.55 clockwise from (29.15, 42.65) to (29.15, 59.75)
  circle C1 centre (-35.875, -20) radius 1.5
  circle C2 centre (-35.875, 20) radius 1.5
  circle C3 centre (4.125, -20) radius 1.5
  circle C4 centre (4.125, 20) radius 1.5
  circle C5 centre (-29.625, 0) radius 1.5
  circle C6 centre (-2.125, 0) radius 1.5
  circle C7 centre (-35.875, 33) radius 1.5
  circle C8 centre (-35.875, 73) radius 1.5
  circle C9 centre (4.125, 33) radius 1.5
  circle C10 centre (4.125, 73) radius 1.5
  circle C11 centre (-29.625, 53) radius 1.5
  circle C12 centre (-2.125, 53) radius 1.5
  circle C13 centre (-88.875, 33) radius 1.5
  circle C14 centre (-88.875, 73) radius 1.5
  circle C15 centre (-48.875, 33) radius 1.5
  circle C16 centre (-48.875, 73) radius 1.5
  circle C17 centre (-82.625, 53) radius 1.5
  circle C18 centre (-55.125, 53) radius 1.5
  circle C19 centre (-88.875, 86) radius 1.5
  circle C20 centre (-88.875, 126) radius 1.5
  circle C21 centre (-48.875, 86) radius 1.5
  circle C22 centre (-48.875, 126) radius 1.5
  circle C23 centre (-82.625, 106) radius 1.5
  circle C24 centre (-55.125, 106) radius 1.5
  circle C25 centre (-35.875, 86) radius 1.5
  circle C26 centre (-35.875, 126) radius 1.5
  circle C27 centre (4.125, 86) radius 1.5
  circle C28 centre (4.125, 126) radius 1.5
  circle C29 centre (-29.625, 106) radius 1.5
  circle C30 centre (-2.125, 106) radius 1.5
  circle C31 centre (-88.875, 139) radius 1.5
  circle C32 centre (-88.875, 179) radius 1.5
  circle C33 centre (-48.875, 139) radius 1.5
  circle C34 centre (-48.875, 179) radius 1.5
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hole "Hole6" HoleDepth 38.1 HoleDiameter 4.4 (= "threadedinsertdiam") TipAngle 180
sketch "Sketch25" plane through (0, 0, 30.35) normal (0, 0, 1) x axis (-1, 0, 0)
  line L1 (-73.525, 79.5) -> (-73.525, 184)
  line L2 (-59.525, 79.5) -> (-73.525, 79.5)
  line L3 (-59.525, 174.475) -> (-59.525, 79.5)
  line L4 (1.475, 174.475) -> (-59.525, 174.475)
  line L5 (1.475, 79.5) -> (1.475, 174.475)
  line L6 (37.7, 79.5) -> (1.475, 79.5)
  line L7 (37.7, 158.6) -> (37.7, 79.5)
  line L8 (-84.3454, 196.7) -> (-0.4, 196.7)
  line L9 (-122.4454, 79.5) -> (-122.4454, 158.6)
  line L10 (-109.7454, 79.5) -> (-122.4454, 79.5)
  line L11 (-109.7454, 100.3273) -> (-109.7454, 79.5)
  line L12 (-109.7454, 158.6) -> (-109.7454, 115.2727)
  line L13 (-73.525, 184) -> (-84.3454, 184)
  circle C1 centre (-105.245, 179.495) radius 1.7
  circle C2 centre (20.495, 179.495) radius 1.7
  circle C3 centre (29.15, 107.8) radius 1.7
  circle C4 centre (-113.9, 107.8) radius 1.7
  arc A1 centre (-0.4, 158.6) radius 38.1 clockwise from (-0.4, 196.7) to (37.7, 158.6)
  arc A2 centre (-84.3454, 158.6) radius 38.1 clockwise from (-122.4454, 158.6) to (-84.3454, 196.7)
  arc A3 centre (-113.9, 107.8) radius 8.55 clockwise from (-109.7454, 115.2727) to (-109.7454, 100.3273)
  arc A4 centre (-84.3454, 158.6) radius 25.4 clockwise from (-109.7454, 158.6) to (-106.4925, 171.0365)
  arc A5 centre (-105.245, 179.495) radius 8.55 clockwise from (-96.7868, 180.7443) to (-106.4925, 171.0365)
  arc A6 centre (-84.3454, 158.6) radius 25.4 clockwise from (-96.7868, 180.7443) to (-84.3454, 184)
  circle C5 centre (7.825, 148.425) radius 1.5
  circle C6 centre (-65.875, 148.425) radius 1.5
  circle C7 centre (-65.875, 96.325) radius 1.5
  circle C8 centre (7.825, 96.325) radius 1.5
  circle C9 centre (7.825, 44.225) radius 1.5
  circle C10 centre (-65.875, 44.225) radius 1.5
hole "Hole7" HoleDepth 22.86 HoleDiameter 4.4 (= "threadedinsertdiam") TipAngle 180
move "Move1"
extrude "Extrude48" new body of existing geometry blind 19.05
extrude "Extrude49" new body of existing geometry blind 16.51
combine "Combine10"
combine "Combine11"
mirror "Mirror6" mirrorStitchTolerance 0.1016
mirror "Mirror7" mirrorStitchTolerance 0.1016
combine "Combine12"
combine "Combine13"
sketch "Sketch26" plane through (0, 0, 30.35) normal (0, 0, -1) x axis (1, 0, 0)
  line L1 (113.9, 116.35) -> (116.1, 116.35)
  line L2 (116.1, 99.25) -> (113.9, 99.25)
  line L3 (116.1, 79.5) -> (116.1, 99.25)
  line L4 (122.45, 79.5) -> (116.1, 79.5)
  line L5 (122.45, 158.6) -> (122.45, 79.5)
  line L6 (0.4, 196.7) -> (84.35, 196.7)
  line L7 (-37.7, 79.5) -> (-37.7, 158.6)
  line L8 (-31.35, 79.5) -> (-37.7, 79.5)
  line L9 (-31.35, 99.25) -> (-31.35, 79.5)
  line L10 (-29.15, 99.25) -> (-31.35, 99.25)
  line L11 (-31.35, 116.35) -> (-29.15, 116.35)
  line L12 (-31.35, 158.6) -> (-31.35, 116.35)
  line L13 (-26.5408, 173.4492) -> (-27.267, 174.1755)
  line L14 (-15.1755, 186.267) -> (-14.4492, 185.5408)
  line L15 (84.35, 190.35) -> (0.4, 190.35)
  line L16 (99.1992, 185.5408) -> (99.9255, 186.267)
  line L17 (112.017, 174.1755) -> (111.2908, 173.4492)
  line L18 (116.1, 116.35) -> (116.1, 158.6)
  line L19 (113.9, 59.75) -> (116.1, 59.75)
  line L20 (116.1, 42.65) -> (113.9, 42.65)
  line L21 (116.1, 0.4) -> (116.1, 42.65)
  line L22 (111.2908, -14.4492) -> (112.017, -15.1755)
  line L23 (99.9255, -27.267) -> (99.1992, -26.5408)
  line L24 (0.4, -31.35) -> (84.35, -31.35)
  line L25 (-14.4492, -26.5408) -> (-15.1755, -27.267)
  line L26 (-27.267, -15.1755) -> (-26.5408, -14.4492)
  line L27 (-31.35, 42.65) -> (-31.35, 0.4)
  line L28 (-29.15, 42.65) -> (-31.35, 42.65)
  line L29 (-31.35, 59.75) -> (-29.15, 59.75)
  line L30 (-31.35, 79.5) -> (-31.35, 59.75)
  line L31 (-37.7, 79.5) -> (-31.35, 79.5)
  line L32 (-37.7, 0.4) -> (-37.7, 79.5)
  line L33 (84.35, -37.7) -> (0.4, -37.7)
  line L34 (122.45, 79.5) -> (122.45, 0.4)
  line L35 (116.1, 79.5) -> (122.45, 79.5)
  line L36 (116.1, 59.75) -> (116.1, 79.5)
  circle C1 centre (113.9, 107.8) radius 2.2
  circle C2 centre (105.245, 179.495) radius 2.2
  circle C3 centre (-20.495, 179.495) radius 2.2
  arc A1 centre (113.9, 107.8) radius 8.55 clockwise from (113.9, 99.25) to (113.9, 116.35)
  arc A2 centre (84.35, 158.6) radius 38.1 clockwise from (84.35, 196.7) to (122.45, 158.6)
  arc A3 centre (0.4, 158.6) radius 38.1 clockwise from (-37.7, 158.6) to (0.4, 196.7)
  arc A4 centre (-29.15, 107.8) radius 8.55 clockwise from (-29.15, 116.35) to (-29.15, 99.25)
  arc A5 centre (0.4, 158.6) radius 31.75 clockwise from (-31.35, 158.6) to (-27.267, 174.1755)
  arc A6 centre (-20.495, 179.495) radius 8.55 clockwise from (-14.4492, 185.5408) to (-26.5408, 173.4492)
  arc A7 centre (0.4, 158.6) radius 31.75 clockwise from (-15.1755, 186.267) to (0.4, 190.35)
  arc A8 centre (84.35, 158.6) radius 31.75 clockwise from (84.35, 190.35) to (99.9255, 186.267)
  arc A9 centre (105.245, 179.495) radius 8.55 clockwise from (111.2908, 173.4492) to (99.1992, 185.5408)
  arc A10 centre (84.35, 158.6) radius 31.75 clockwise from (112.017, 174.1755) to (116.1, 158.6)
  circle C4 centre (-29.15, 107.8) radius 2.2
  circle C5 centre (113.9, 51.2) radius 2.2
  circle C6 centre (105.245, -20.495) radius 2.2
  circle C7 centre (-20.495, -20.495) radius 2.2
  circle C8 centre (-29.15, 51.2) radius 2.2
  arc A11 centre (113.9, 51.2) radius 8.55 clockwise from (113.9, 42.65) to (113.9, 59.75)
  arc A12 centre (84.35, 0.4) radius 31.75 clockwise from (116.1, 0.4) to (112.017, -15.1755)
  arc A13 centre (105.245, -20.495) radius 8.55 clockwise from (99.1992, -26.5408) to (111.2908, -14.4492)
  arc A14 centre (84.35, 0.4) radius 31.75 clockwise from (99.9255, -27.267) to (84.35, -31.35)
  arc A15 centre (0.4, 0.4) radius 31.75 clockwise from (0.4, -31.35) to (-15.1755, -27.267)
  arc A16 centre (-20.495, -20.495) radius 8.55 clockwise from (-26.5408, -14.4492) to (-14.4492, -26.5408)
  arc A17 centre (0.4, 0.4) radius 31.75 clockwise from (-27.267, -15.1755) to (-31.35, 0.4)
  arc A18 centre (-29.15, 51.2) radius 8.55 clockwise from (-29.15, 59.75) to (-29.15, 42.65)
  arc A19 centre (0.4, 0.4) radius 38.1 clockwise from (0.4, -37.7) to (-37.7, 0.4)
  arc A20 centre (84.35, 0.4) radius 38.1 clockwise from (122.45, 0.4) to (84.35, -37.7)
extrude "Extrude50" cut sketch "Sketch26" profile of C1 C2 C3 C4 C5 C6 C7 C8 against normal blind 165.1
component_from_bodies "Body->Comp1"
copy_paste_bodies "CutPasteBodies1"
component_from_bodies "Body->Comp2"
component_from_bodies "Body->Comp3"
copy_paste_bodies "CutPasteBodies1"
copy_paste_bodies "CutPasteBodies1"
component_from_bodies "Body->Comp4"
copy_paste_bodies "CutPasteBodies1"
copy_paste "CutPaste1"
copy_paste "CutPaste1"
copy_paste "CutPaste2"
copy_paste "CutPaste3"
copy_paste "CutPaste4"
